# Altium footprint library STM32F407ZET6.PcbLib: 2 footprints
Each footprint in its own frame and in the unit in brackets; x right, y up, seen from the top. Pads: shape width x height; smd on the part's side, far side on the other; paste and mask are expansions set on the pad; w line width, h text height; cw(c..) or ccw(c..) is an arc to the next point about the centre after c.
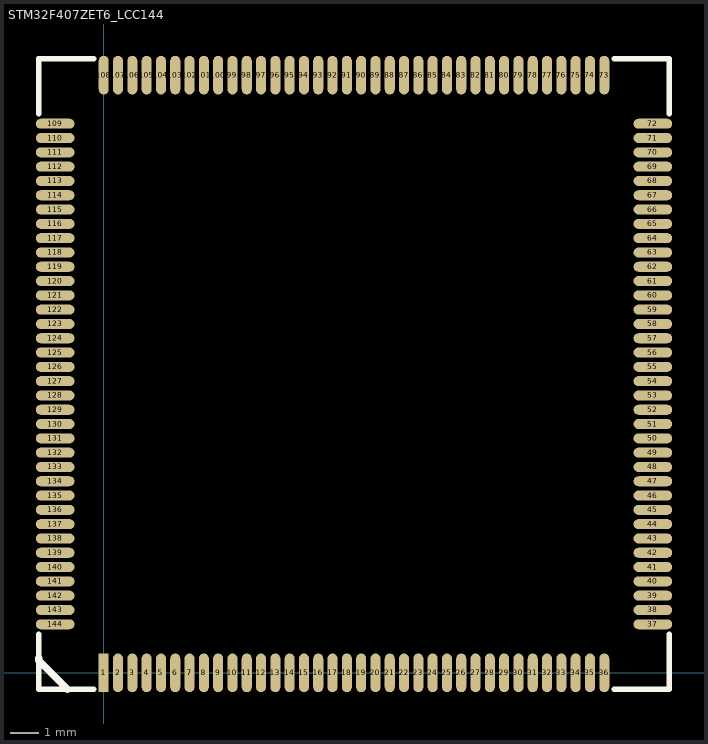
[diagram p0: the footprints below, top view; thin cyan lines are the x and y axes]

## PCBComponent_1 [mm]

## STM32F407ZET6_LCC144 [mm]
pads (144):
  rect 0.35x1.35 smd: 1(0,0)
  oval 0.35x1.35 smd: 2(0.5,0) 3(1,0) 4(1.5,0) 5(2,0) 6(2.5,0) 7(3,0) 8(3.5,0) 9(4,0) 10(4.5,0) 11(5,0) 12(5.5,0) 13(6,0) 14(6.5,0) 15(7,0) 16(7.5,0) 17(8,0) 18(8.5,0) 19(9,0) 20(9.5,0) 21(10,0) 22(10.5,0) 23(11,0) 24(11.5,0) 25(12,0) 26(12.5,0) 27(13,0) 28(13.5,0) 29(14,0) 30(14.5,0) 31(15,0) 32(15.5,0) 33(16,0) 34(16.5,0) 35(17,0) 36(17.5,0) 73(17.5,20.9) 74(17,20.9) 75(16.5,20.9) 76(16,20.9) 77(15.5,20.9) 78(15,20.9) 79(14.5,20.9) 80(14,20.9) 81(13.5,20.9) 82(13,20.9) 83(12.5,20.9) 84(12,20.9) 85(11.5,20.9) 86(11,20.9) 87(10.5,20.9) 88(10,20.9) 89(9.5,20.9) 90(9,20.9) 91(8.5,20.9) 92(8,20.9) 93(7.5,20.9) 94(7,20.9) 95(6.5,20.9) 96(6,20.9) 97(5.5,20.9) 98(5,20.9) 99(4.5,20.9) 100(4,20.9) 101(3.5,20.9) 102(3,20.9) 103(2.5,20.9) 104(2,20.9) 105(1.5,20.9) 106(1,20.9) 107(0.5,20.9) 108(0,20.9)
  oval 1.35x0.35 smd: 37(19.2,1.7) 38(19.2,2.2) 39(19.2,2.7) 40(19.2,3.2) 41(19.2,3.7) 42(19.2,4.2) 43(19.2,4.7) 44(19.2,5.2) 45(19.2,5.7) 46(19.2,6.2) 47(19.2,6.7) 48(19.2,7.2) 49(19.2,7.7) 50(19.2,8.2) 51(19.2,8.7) 52(19.2,9.2) 53(19.2,9.7) 54(19.2,10.2) 55(19.2,10.7) 56(19.2,11.2) 57(19.2,11.7) 58(19.2,12.2) 59(19.2,12.7) 60(19.2,13.2) 61(19.2,13.7) 62(19.2,14.2) 63(19.2,14.7) 64(19.2,15.2) 65(19.2,15.7) 66(19.2,16.2) 67(19.2,16.7) 68(19.2,17.2) 69(19.2,17.7) 70(19.2,18.2) 71(19.2,18.7) 72(19.2,19.2) 109(-1.7,19.2) 110(-1.7,18.7) 111(-1.7,18.2) 112(-1.7,17.7) 113(-1.7,17.2) 114(-1.7,16.7) 115(-1.7,16.2) 116(-1.7,15.7) 117(-1.7,15.2) 118(-1.7,14.7) 119(-1.7,14.2) 120(-1.7,13.7) 121(-1.7,13.2) 122(-1.7,12.7) 123(-1.7,12.2) 124(-1.7,11.7) 125(-1.7,11.2) 126(-1.7,10.7) 127(-1.7,10.2) 128(-1.7,9.7) 129(-1.7,9.2) 130(-1.7,8.7) 131(-1.7,8.2) 132(-1.7,7.7) 133(-1.7,7.2) 134(-1.7,6.7) 135(-1.7,6.2) 136(-1.7,5.7) 137(-1.7,5.2) 138(-1.7,4.7) 139(-1.7,4.2) 140(-1.7,3.7) 141(-1.7,3.2) 142(-1.7,2.7) 143(-1.7,2.2) 144(-1.7,1.7)
Top Overlay:
  lines w0.2: -2.275,1.35 -2.275,-0.575 -0.35,-0.575 ; -2.275,19.55 -2.275,21.474 ; -0.35,21.475 -2.274,21.475 ; 17.85,-0.575 19.775,-0.575 19.775,1.35 ; 17.85,21.475 19.775,21.475 19.775,19.55 ; -2.275,21.474 -2.274,21.475
  lines w0.254: -2.275,0.508 -2.275,0.43 -1.27,-0.575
